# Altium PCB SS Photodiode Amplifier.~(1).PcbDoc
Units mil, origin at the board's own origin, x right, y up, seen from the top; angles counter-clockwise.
Board outline 2000 x 1500 mil, 2 copper layers (Top Layer, Bottom Layer), stack 62 mil thick; 22 components, 10 nets, 61 pads, 2 vias.
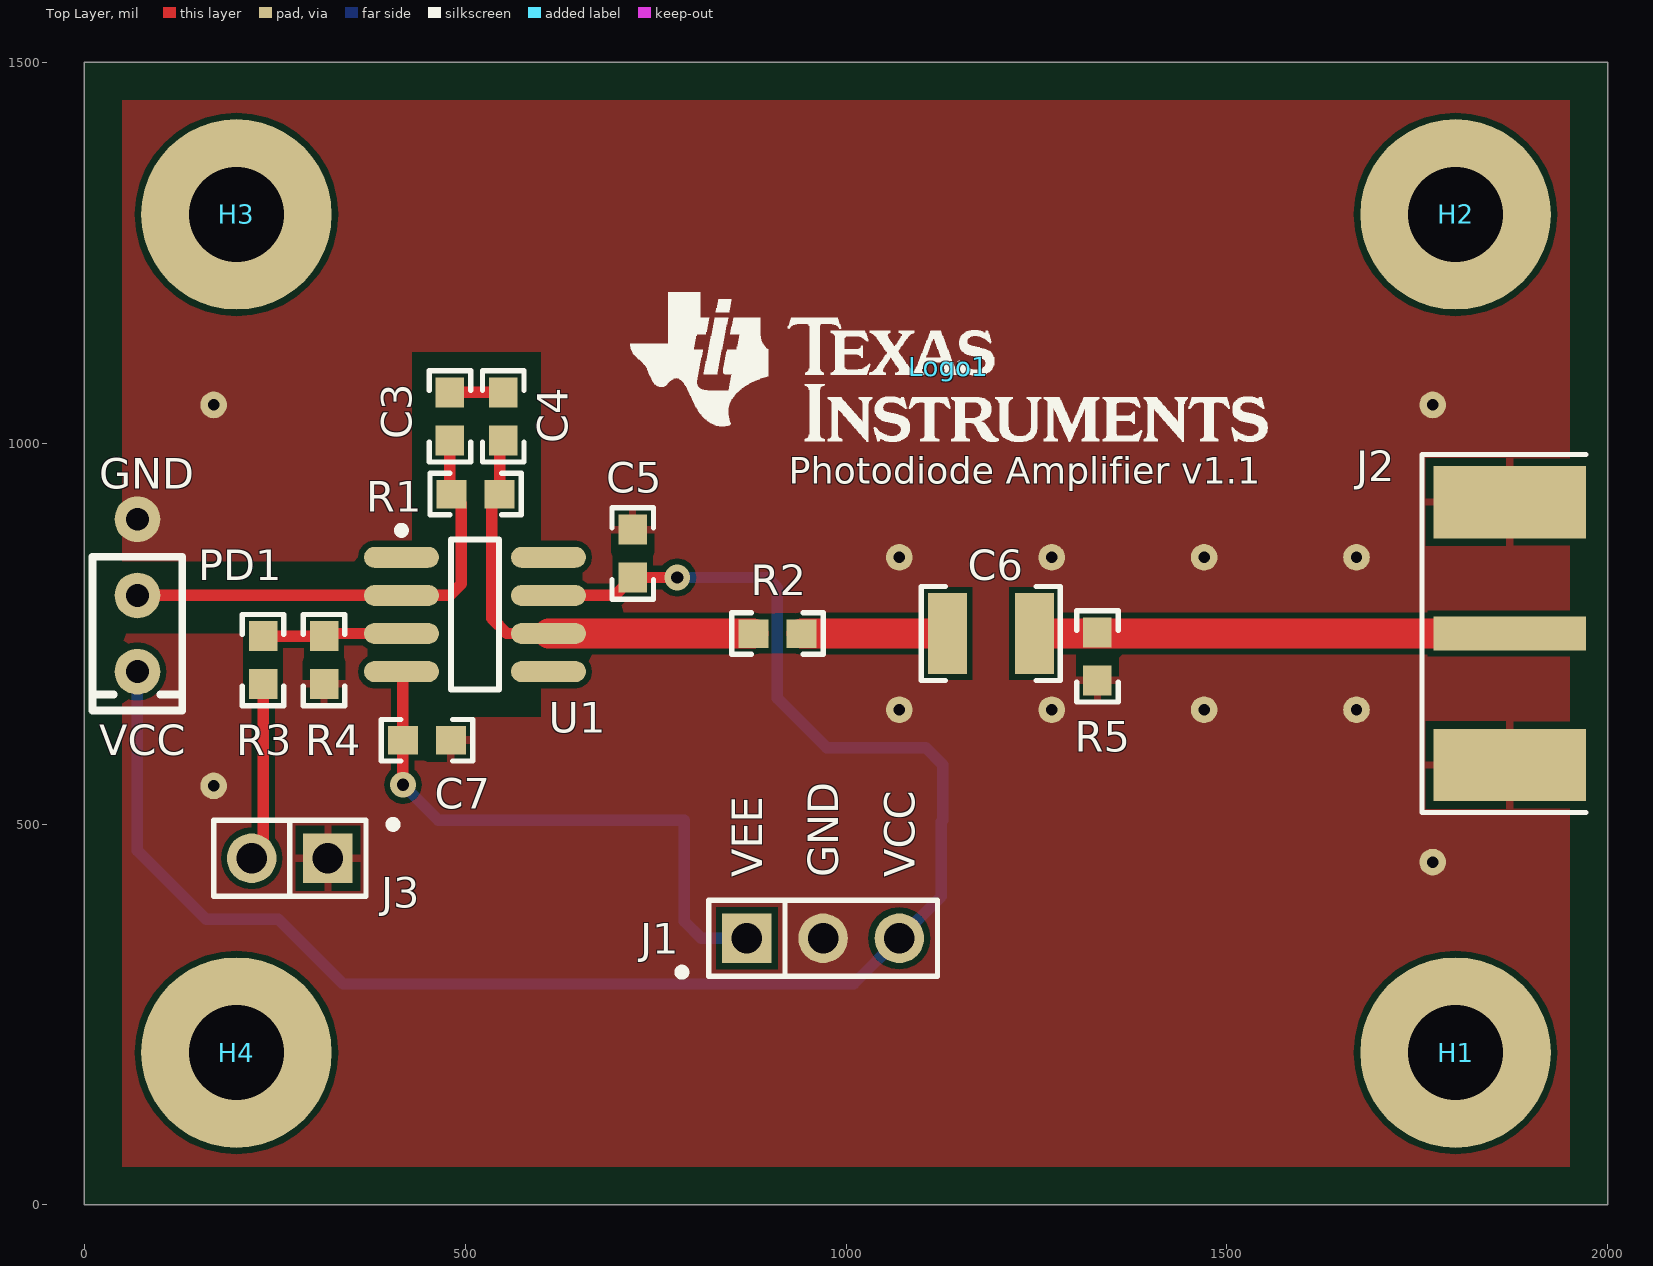
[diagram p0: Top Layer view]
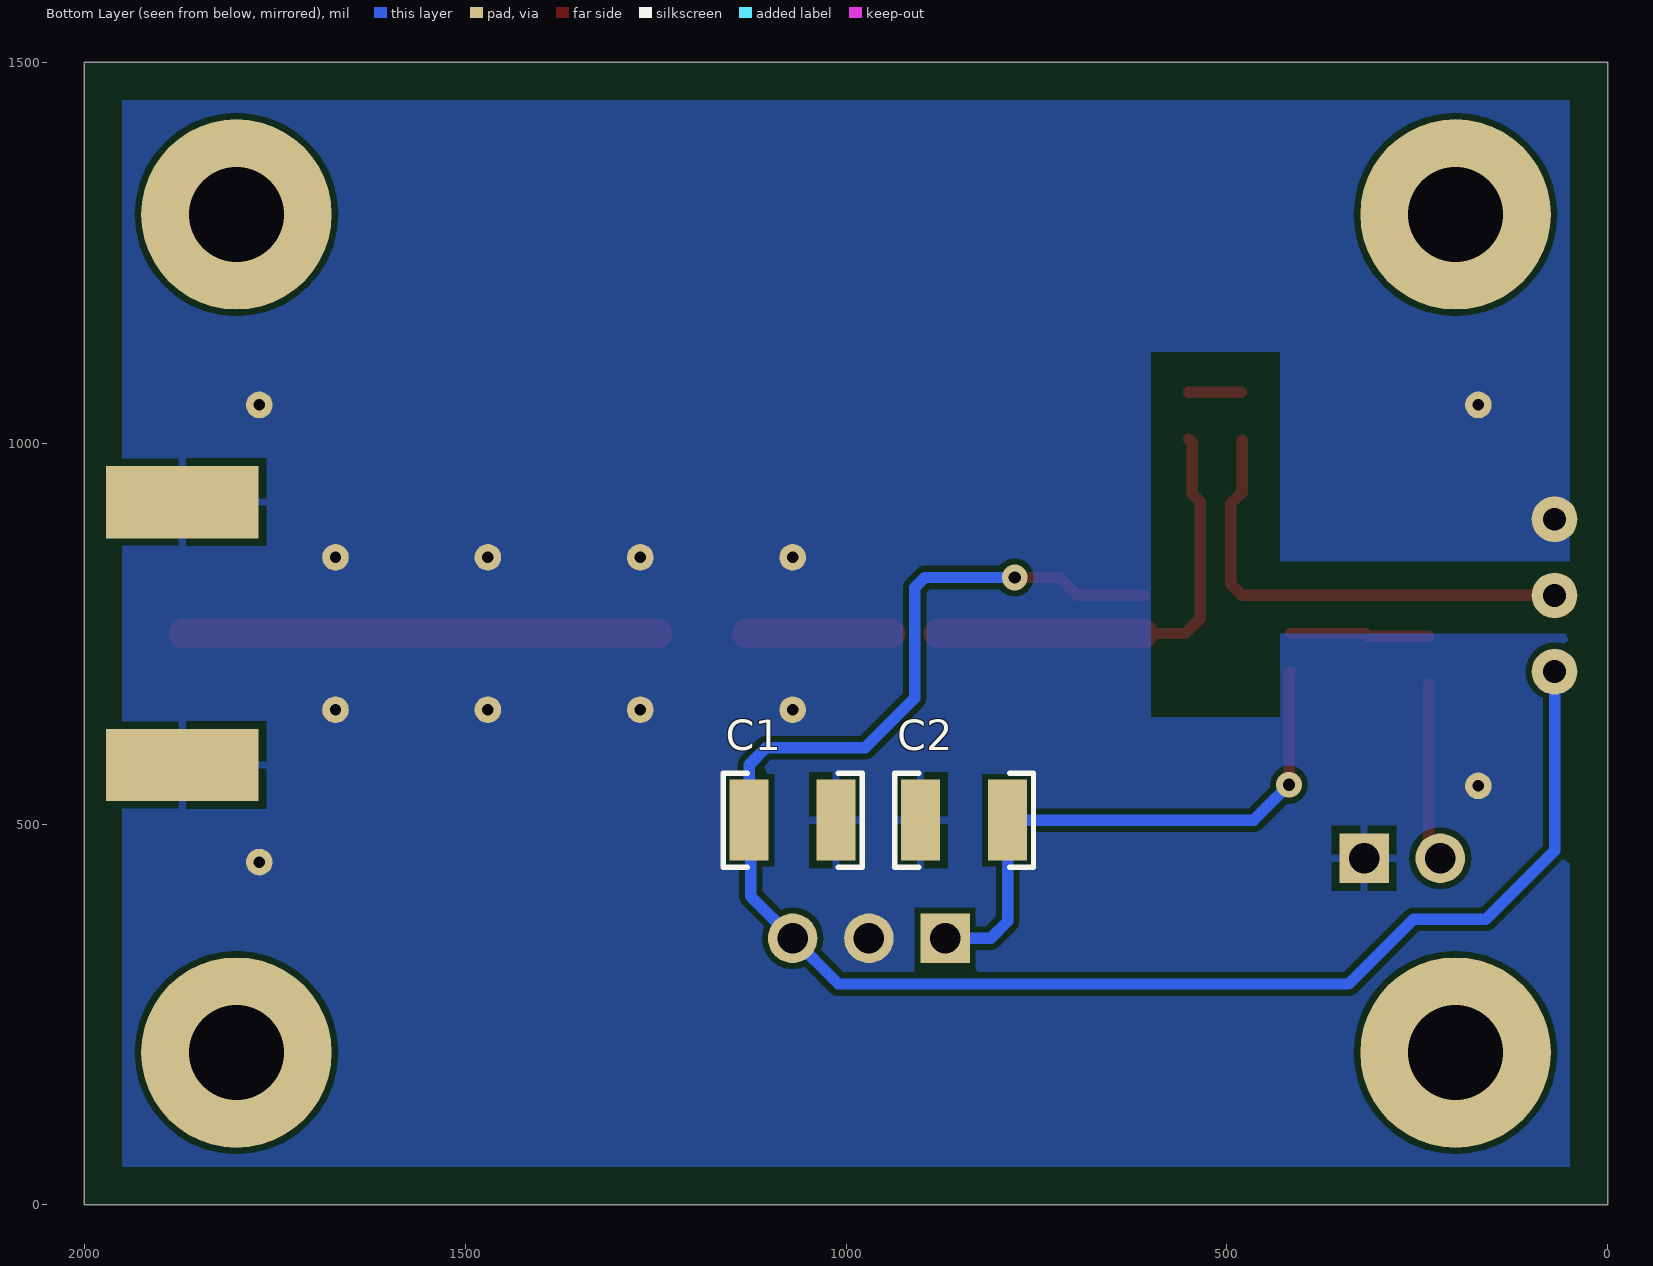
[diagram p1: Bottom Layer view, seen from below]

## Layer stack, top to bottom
Top Layer: signal copper 1.4
Dielectric: core 59.2, FR-4, Dk 4.8
Bottom Layer: signal copper 1.4

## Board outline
0,0 2000,0 2000,1500 0,1500

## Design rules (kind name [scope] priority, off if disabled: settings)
AcuteAngle [All] p1: minimum=4.50000000000000E+0001 checktracksonly=FALSE
AssemblyTestPointUsage [All] p1: valid=2
Clearance "Transmission Line Clearance" [(InNet('NetC3_1') OR InNet('NETC5_1') OR InNet('NETC5_2'))] p1: gap=6
Clearance Clearance_BoardEdge_MountingHoles [OnCopper and InComponentClass('Mounting Holes') vs IsKeepOut] p2: gap=40
Clearance Clearance_BoardEdge_Poly [OnCopper and InPoly vs IsKeepOut] p3: gap=25
Clearance Clearance_BoardEdge [OnCopper and Not InComponentClass('Logo') and not InComponentClass('FiducialMark') and not InRegion(1000,500,4000,800) vs IsKeepOut] p4: gap=75
Clearance [All] p5: gap=8
ComponentClearance ComponentClearance_Logo [InComponentClass(Logo)] p1: gap=50 collisioncheckmode=3 verticalgap=10 showdistances=FALSE
ComponentClearance ComponentClearance_ScrewToNut [(HasFootprint('NY PMS 440 0025 PH')) vs (HasFootprint('Keystone_1902C'))] p2: gap=5 collisioncheckmode=3 verticalgap=10 showdistances=FALSE
ComponentClearance ComponentClearance_MountingHoles [InComponentClass('Mounting Holes')] p3: gap=250 collisioncheckmode=3 verticalgap=100000 showdistances=FALSE
ComponentClearance ComponentClearance_SmallPassives [HasFootprint('0201*') or HasFootprint('0402*') or HasFootprint('0508') or HasFootprint('0603*') or HasFootprint('0612') or HasFootprint('0805*') or HasFootprint('0815*') or HasFootprint('0830*') or HasFootprint('1206*') or HasFootprint('1210*') or HasFootprint('1808*') or HasFootprint('1812*') or HasFootprint('1825*') or HasFootprint('2010*') or HasFootprint('2220*') or HasFootprint('2225*') or HasFootprint('2512*') or HasFootprint('2728*') or HasFootprint('3518*') vs HasFootprint('0201*') or HasFootprint('0402*') or HasFootprint('0508') or HasFootprint('0603*') or HasFootprint('0612') or HasFootprint('0805*') or HasFootprint('0815*') or HasFootprint('0830*') or HasFootprint('1206*') or HasFootprint('1210*') or HasFootprint('1808*') or HasFootprint('1812*') or HasFootprint('1825*') or HasFootprint('2010*') or HasFootprint('2220*') or HasFootprint('2225*') or HasFootprint('2512*') or HasFootprint('2728*') or HasFootprint('3518*')] p4: gap=10 collisioncheckmode=3 verticalgap=10 showdistances=FALSE
ComponentClearance ComponentClearance_THtoSMT [IsThruComponent vs IsSMTComponent] p5: gap=10 collisioncheckmode=3 verticalgap=100000 showdistances=FALSE
ComponentClearance ComponentClearance_THtoTH [IsThruComponent vs IsThruComponent] p6: gap=10 collisioncheckmode=3 verticalgap=100000 showdistances=FALSE
ComponentClearance [All] p7: gap=40 collisioncheckmode=3 verticalgap=10 showdistances=FALSE
DiffPairsRouting [All] p1: maxlimit=100 minlimit=10 mostfreqgap=10 maxuncoupledlength=1000
FabricationTestPointUsage TestPointUsage [All] p1: valid=2 allowmultiple=FALSE
FabricationTestpoint Testpoint [All] p1: side=3 testpointundercomponent=TRUE minsize=40 maxsize=100 preferedsize=60 minholesize=0 maxholesize=40 preferedholesize=32 testpointgrid=1 allowsidetop=TRUE allowsidebottom=TRUE usegrid=TRUE gridtolerance=0.01
FanoutControl Fanout_LCC [IsLCC] p1: bgadir=Out bgaviamode=Centered fanoutstyle=Auto fanoutdirection=Alternating viagrid=1 // Fanout_LCC (Default Rule)
FanoutControl Fanout_BGA [IsBGA] p2: bgadir=Out bgaviamode=Centered fanoutstyle=Auto fanoutdirection=Alternating viagrid=1 // Fanout_BGA (Default Rule)
FanoutControl Fanout_Default [All] p4: bgadir=Out bgaviamode=Centered fanoutstyle=Auto fanoutdirection=Alternating viagrid=1 // Fanout_Default (Default Rule)
FanoutControl Fanout_Small [(CompPinCount < 5)] p5: bgadir=Out bgaviamode=Centered fanoutstyle=Auto fanoutdirection=OutThenIn viagrid=1 // Fanout_Small (Default Rule)
HoleSize [All] p1: absolutevalues=TRUE maxlimit=251 minlimit=8 maxpercent=80.000 minpercent=20.000
MinimumAnnularRing [All] p1: minimumring=9
MinimumSolderMaskSliver MinimumSolderMaskSliver_Logo [InComponentClass('Logo') vs InComponentClass('Logo')] p1: minsoldermaskwidth=0.7
MinimumSolderMaskSliver [All] p2: minsoldermaskwidth=4
PlaneConnect [All] p1: planeconnectstyle=Relief reliefexpansion=10 reliefentries=4 reliefconductorwidth=10 reliefairgap=10
PolygonConnect GNDVia [InPadClass('GNDVia')] p1: connectstyle=Direct reliefconductorwidth=10 reliefentries=4 polygonreliefangle="90 Angle" airgapwidth=10
PolygonConnect "SMA GND" [(InComponent('J1') AND InNet('GND'))] p2: connectstyle=Direct reliefconductorwidth=10 reliefentries=4 polygonreliefangle="90 Angle" airgapwidth=10
PolygonConnect [All] p3: connectstyle=Relief reliefconductorwidth=10 reliefentries=4 polygonreliefangle="90 Angle" airgapwidth=10
RoutingVias [All] p1: holewidth=16 width=34 viastyle="Through Hole" minholewidth=8 minwidth=26 maxholewidth=40 maxwidth=65
SMDToCorner [All] p1: distance=30000
SilkToSilkClearance [All] p1: silktosilkclearance=5
SilkscreenOverComponentPads [All] p1: minsilkscreentomaskgap=5
SolderMaskExpansion [All] p1: expansion=3
Width [All] p1: maxlimit=100 minlimit=6 preferedwidth=15 checkconnectedcopper=TRUE
14 further rules are at their usual default settings.

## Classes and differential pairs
component class Logo: Logo1
component class OPA172PDA_Hardware_ANSI-B: Logo1
component class Header: J1 J3
component class OPA172PDA: C1 C2 C3 C4 C6 C7 H1 H2 H3 H4 J2 J3 PD1 R1 R2 R3 R4 R5 U1
pad class GNDVia: Free-0 Free-1 Free-2 Free-3 Free-4 Free-5 Free-6

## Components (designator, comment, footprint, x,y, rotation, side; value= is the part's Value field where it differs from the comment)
C1 "C1210C106K8PACTU" 1210 1070,505 r180 bottom
C2 "C1210C106K8PACTU" 1210 845,505 r180 bottom
C3 "06033C101KAT2A" 0603 480,1035 r270 top
C4 "06033C101KAT2A" 0603 550,1035 r270 top
C5 "0603YC104JAT2A" 0603 720,855 r270 top
C6 "12103D226MAT2A" 1210 1190,750 r180 top
C7 "0603YC104JAT2A" 0603 450,610 r180 top
H1 "NA" "Mounting Hole" 1800,200 r0 top
H2 "NA" "Mounting Hole" 1800,1300 r0 top
H3 "NA" "Mounting Hole" 200,1300 r0 top
H4 "NA" "Mounting Hole" 200,200 r0 top
J1 "TSW-103-07-G-S" TSW-103-07-G-S 970,350 r0 top
J2 "142-0701-851" Emerson_142-0701-851 1871,750 r270 top
J3 "TSW-102-07-G-S" TSW-102-07-G-S 270,455 r180 top
Logo1 "Texas Instruments" TI_Stacked_Overlay_Small 1135,1100 r0 top
PD1 "PDB-C156" PDB-C156 70,750 r180 top
R1 "CRCW060310K0FKEA" 0603 514,933 r0 top
R2 "CRCW060351R1FKEA" 0603 910,750 r0 top
R3 "CRCW060310R0FKEA" 0603 235,715 r90 top
R4 "CRCW060310R0FKEA" 0603 315,715 r90 top
R5 "CRCW0603100KFKEA" 0603 1330,720 r90 top
U1 "OPA172" M08A_M 513,775 r0 top

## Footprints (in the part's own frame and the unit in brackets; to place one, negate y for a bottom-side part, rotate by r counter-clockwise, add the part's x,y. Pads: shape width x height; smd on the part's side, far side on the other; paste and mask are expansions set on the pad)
0603 [mm] "0603 from SM-752 data"
  rect 1x0.95 smd: 1(-0.8,0) 2(0.8,0)
  silkscreen extent -1.52,-0.69 1.52,0.69, body extent -0.87,-0.47 0.87,0.47, height 0.85
1210 [mm] "1210 from SM-752 data"
  rect 1.3x2.7 smd: 1(-1.45,0) 2(1.45,0)
  silkscreen extent -2.32,-1.57 2.32,1.57, body extent -1.7,-1.35 1.7,1.35, height 1.35
Emerson_142-0701-851 [mil] "Johnson Components"
  rect 45x200 smd: 1(0,0)
  rect 95x200 smd: 2(-172.5,0) 3(172.5,0)
  rect 95x200 smd far side: 4(172.5,0) 5(-172.5,0)
  silkscreen extent -235,-115 235,100, body extent -190,-95 190,487, height 155
M08A_M [mm] "SOIC, 8-Leads, Body 4.9x3.9mm, Pitch 1.27mm, IPC Low Density"
  oval 2.5x0.7 smd: 1(-2.45,1.905) 2(-2.45,0.635) 3(-2.45,-0.635) 4(-2.45,-1.905) 5(2.45,-1.905) 6(2.45,-0.635) 7(2.45,0.635) 8(2.45,1.905)
  silkscreen extent -2.57,-2.5 0.8,2.93, body extent -2,-2.5 2,2.5, height 1.75
"Mounting Hole" [mil]
  round 250 hole 125: 1(0,0)
PDB-C156 [mil] "Photodiode"
  round 60 hole 30: 1(0,50) 2(0,-50)
  silkscreen extent -59,-101 59,101
TI_Stacked_Overlay_Small [mil]
  silkscreen extent -418,-98 418,98
TSW-102-07-G-S [mm] "Samtec 100mil, 1x2, 230 mil above insulator"
  rect 1.65x1.65 hole 1.016 mask+0: 1(-1.27,0)
  round 1.65 hole 1.016 mask+0: 2(1.27,0)
  silkscreen extent -3.57,-1.27 2.54,1.27, body extent -2.54,-1.27 2.54,1.27, height 8.38
TSW-103-07-G-S [mm] "Samtec 100mil, 1x3, 230 mil above insulator"
  rect 1.65x1.65 hole 1.016 mask+0: 1(-2.54,0)
  round 1.65 hole 1.016 mask+0: 2(0,0) 3(2.54,0)
  silkscreen extent -4.83,-1.27 3.81,1.27, body extent -3.81,-1.27 3.81,1.27, height 8.38

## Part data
C1 C2: "CAP, CERM, 10uF, 10V, +/-10%, X5R, 1210"
C3 C4: "CAP, CERM, 100pF, 25V, +/-10%, X7R, 0603"
C5 C7: "CAP, CERM, 0.1uF, 16V, +/-5%, X7R, 0603"
C6: "CAP, CERM, 22uF, 25V, +/-20%, X5R, 1210"
H1 H2 H3 H4: library part "Mounting Hole", "Mounting Hole"
J1: "Header, TH, 100mil, 3x1, Gold plated, 230 mil above insulator"
J2: "Connector, SMT, End launch SMA 50 ohm"
J3: "Header, TH, 100mil, 2x1, Gold plated, 230 mil above insulator"
Logo1: library part TI_Logo, "Texas Instrument Corporate Signature"
PD1: "Photodiode"
R1: "RES, 10.0k ohm, 1%, 0.1W, 0603"
R2: "RES, 51.1 ohm, 1%, 0.1W, 0603"
R3 R4: "RES, 10.0 ohm, 1%, 0.1W, 0603"
R5: "RES, 100k ohm, 1%, 0.1W, 0603"

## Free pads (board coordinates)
  round 60 hole 30: 0(70,900)
  round 35 hole 15: 0(1070,650) 0(1670,850) 0(1770,450) 1(1470,850) 1(1770,1050) 2(170,1050) 2(1270,850) 3(170,550) 3(1070,850) 4(1670,650) 5(1470,650) 6(1270,650)

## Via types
v1: diameter 34, hole 16, Top Layer to Bottom Layer, 2 vias

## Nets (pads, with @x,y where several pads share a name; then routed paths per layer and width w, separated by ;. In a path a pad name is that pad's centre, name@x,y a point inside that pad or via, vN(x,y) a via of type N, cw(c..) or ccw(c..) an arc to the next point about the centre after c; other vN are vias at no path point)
GND: C1.2 C2.1 C5.1 C7.1 J1.2 J2.2 J2.3 J2.4 J2.5 J3.1 pad.0 pad.1 pad.2 pad.3 pad.4 pad.5 pad.6 R4.1 R5.1
NetC3_1: C3.1 C4.1 | length 68.5
  Top Layer w15: C3.1@481.5,1066.5 C4.1
NetC3_2: C3.2 PD1.2 R1.1 U1.2 | length 622.9
  Top Layer w15: PD1.2 U1.2 480,800 495,815 495,920.5 R1.1 ; R1.1@480,935 C3.2
NetC4_2: C4.2 R1.2 R2.1 U1.6 | length 592.5
  Top Layer w15: C4.2@550,1005 545.5,1000.5 R1.2 535,922.5 535,770 555,750 U1.6
  Top Layer w39: U1.6@610,750 R2.1
NetC6_1: C6.1 J2.1 R5.2 | length 622.9
  Top Layer w39: C6.1 J2.1@1870,750
NetC6_2: C6.2 R2.2 | length 188.5
  Top Layer w39: R2.2 C6.2@1130,750
NetJ3_2: J3.2 R3.1 | length 234.7
  Top Layer w15: J3.2 235,470 R3.1
NetR3_2: R3.2 R4.2 U1.3 | length 183
  Top Layer w15: R3.2 R4.2 318.5,750 U1.3
VCC: C1.1 C5.2 J1.3 PD1.1 U1.7 | length 2295
  Top Layer w15: U1.7 696.5,800 C5.2 v1(778.5,823.5)
  Bottom Layer w15: PD1.1 70,465 160,375 255,375 340,290 1010,290 J1.3 1125,405 C1.1@1125,502.91 ; v1(778.5,823.5) 896.5,823.5 910,810 910,665 975,600 1105,600 1127.09,577.91 C1.1
VEE: C2.2 C7.2 J1.1 U1.4 | length 762.1
  Top Layer w15: U1.4 418.5,698.04 C7.2 v1(418.5,551.5)
  Bottom Layer w15: v1(418.5,551.5) 465,505 C2.2 787.91,372.09 810,350 J1.1
pads on no net: H1.1 H2.1 H3.1 H4.1 U1.1 U1.5 U1.8

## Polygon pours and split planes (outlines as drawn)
GND on Top Layer "Top Layer GND" (solid, pour order 4): 50,1450 50,50 1950,50 1950,1450
GND on Bottom Layer "Bottom Layer GND" (solid, pour order 3): 50,1450 50,50 1950,50 1950,1450

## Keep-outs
Keep-Out Layer:
  lines w10: -5,3450 cw(c0,3450) 0,3455 ; -5,3450 cw(c0,3450) 0,3455 ; -5,3450 cw(c0,3450) 0,3455 ; -5,3450 cw(c0,3450) 0,3455 ; -5,3450 cw(c0,3450) 0,3455 ; -5,3450 cw(c0,3450) 0,3455 ; 4950,-5 ccw(c4950,0) 4955,0 ; 4950,-5 ccw(c4950,0) 4955,0 ; 4950,-5 ccw(c4950,0) 4955,0 ; 4950,-5 ccw(c4950,0) 4955,0 ; 4950,-5 ccw(c4950,0) 4955,0 ; 4950,-5 ccw(c4950,0) 4955,0 ; 4950,3455 cw(c4950,3450) 4955,3450 ; 4950,3455 cw(c4950,3450) 4955,3450 ; 4950,3455 cw(c4950,3450) 4955,3450 ; 4950,3455 cw(c4950,3450) 4955,3450 ; 4950,3455 cw(c4950,3450) 4955,3450 ; 4950,3455 cw(c4950,3450) 4955,3450
  text ".Layer_Name" at 577,-858.49 h60

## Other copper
Top Layer:
  pour cut-out: 430,1120 430,640 600,640 600,1120
  pour cut-out: 20,750 430,750 430,845 20,845
Bottom Layer:
  pour cut-out: 430,1120 430,640 600,640 600,1120
  pour cut-out: 20,750 430,750 430,845 20,845

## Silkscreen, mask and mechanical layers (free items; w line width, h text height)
Top Overlay:
  text "GND" at 20,940 h40
  text "Photodiode Amplifier v1.1" at 925,935 h60
  text "VCC" at 20,590 h40
  text "VEE" at 890,430 h40 r90
  text "GND" at 990,430 h40 r90
  text "VCC" at 1090,430 h40 r90
Top Paste:
  text ".Layer_Name" at 577,-858.49 h60
Bottom Paste:
  text ".Layer_Name" at 577,-858.49 h60
Drill Guide:
  text ".Layer_Name" at 577,-858.49 h60
M1 Board Outline:
  the board outline again, w10
M2 Board Dimensions:
  rectangle: 124.5,-410.5 499.5,-285.5
  rectangle: -0.5,-285.5 124.5,-160.5
  lines w7: -0.5,-285.5 999.5,-285.5 ; 124.5,-410.5 124.5,-160.5 ; 249.5,-410.5 249.5,-160.5 ; 499.5,-410.5 499.5,-160.5 ; 749.5,-410.5 749.5,-160.5 ; -0.5,-410.5 -0.5,-160.5 999.5,-160.5 999.5,-410.5 -0.5,-410.5
  lines w10: -0.5,-475.5 -0.5,-455.5 ; 59.5,-485.5 -0.5,-465.5 ; 59.5,-445.5 -0.5,-465.5 ; 223.58,-465.5 -0.5,-465.5 ; 775.42,-465.5 999.5,-465.5 ; 939.5,-485.5 999.5,-465.5 ; 939.5,-445.5 999.5,-465.5 ; 999.5,-475.5 999.5,-455.5
  text "1000 (mil)" at 233.58,-501.49 h60
  text ".Layer_Name" at 577,-858.49 h60
M3 3D STEP Top:
  text ".Layer_Name" at 577,-858.49 h60
M4 3D STEP Bottom:
  text ".Layer_Name" at 577,-858.49 h60
M5 Assembly Top:
  lines w7: 4210,929.26 5335,929.26 ; 4210,1051.76 5332.5,1051.76 ; 4910,1171.76 4210,1171.76 5335,1171.76 ; 5139,353 5139,-9.5 ; 5454,-9.5 5454,353 ; 5839,-9.5 5139,-9.5 ; 6264,353 6264,-9.5 5139,-9.5
  lines w10: -292,-930.17 6308,-930.17 ; -292,-726.83 6310,-726.83 ; -292,-523.5 -292,-1133.5 3713,-1133.5 6310,-1133.5 6310,-523.5 -291.5,-523.5 -291.5,-1133.5 1284,-1133.5 ; 2173,-1133.5 2173,-523.5 ; 3440,-726.83 3440,-523.5 ; 4280,-726.83 4280,-523.5 ; 4902,-1140 4902,-937.17
  text "TABLE 1" at 4597.5,1206.76 h40
  text "Label text" at 4662,1112 h40
  text "Variant" at 4235,1096.76 h40
  text "001" at 4302.5,976.76 h40
  text "ChangeMe!" at 4580,974.26 h40
  text "002" at 4302.5,851.76 h40
  text "ChangeMe!" at 4575,849.26 h40
  text "COMPONENTS MARKED 'DNP' SHOULD NOT BE POPULATED, AND MAY NOT BE IN BILL OF MATERIALS" at 1153.5,-318.5 h60
  text "ASSEMBLY VARIANT:" at 1153,-434 h60
  text ".VariantName" at 2189,-434 h60
  text "PCB VIEWED FROM TOP SIDE" at -228.5,-655.67 h60
  text "BOARD #:" at 2248,-655.67 h60
  text ".PRJ_Number" at 2793.5,-655.67 h60
  text "REV:" at 3638,-655.67 h60
  text ".PCB_Rev" at 3929.5,-655.67 h60
  text "SVN REV:" at 4476,-655.67 h60
  text ".VersionControl_RevNumber" at 4982,-655.67 h60
  text "IGNORE ->" at -228.5,-858.49 h60
  text "PLOT NAME =" at -228.5,-1064.34 h60
  text ".plot_File_Name" at 577,-1064.34 h60
  text "GENERATED    :" at 2250,-1064.34 h60
  text ".Print_Date" at 3119.5,-1064.34 h60
  text ".Print_Time" at 3848.5,-1064.34 h60
  text "TEXAS INSTRUMENTS" at 5113,-1064.34 h60
M6 Assembly Bottom:
  lines w10: -292.5,-727.33 6309.5,-727.33 ; -290.5,-930.67 6309.5,-930.67 ; 1115.5,-1140.5 1115.5,-937.67 ; 1737.5,-727.33 1737.5,-524 ; 2577.5,-727.33 2577.5,-524 ; 3844.5,-1134 3844.5,-524 ; 4733.5,-1134 6309,-1134 6309,-524 -292.5,-524 -292.5,-1134 2304.5,-1134 6309.5,-1134 6309.5,-524
  text "COMPONENTS MARKED 'DNP' SHOULD NOT BE POPULATED, AND MAY NOT BE IN BILL OF MATERIALS" at 6102,-318 h60
  text ".VariantName" at 5058,-434 h60
  text "ASSEMBLY VARIANT:" at 6097,-434 h60
  text ".VersionControl_RevNumber" at 1035.5,-656.17 h60
  text "SVN REV:" at 1541.5,-656.17 h60
  text ".PCB_Rev" at 2088,-656.17 h60
  text "REV:" at 2379.5,-656.17 h60
  text ".PRJ_Number" at 3224,-656.17 h60
  text "BOARD #:" at 3769.5,-656.17 h60
  text "PCB VIEWED FROM BOTTOM SIDE" at 6246,-656.17 h60
  text "IGNORE ->" at 2547.85,-858.49 h60
  text "TEXAS INSTRUMENTS" at 904.5,-1064.84 h60
  text ".Print_Time" at 2169,-1064.84 h60
  text ".Print_Date" at 2898,-1064.84 h60
  text "GENERATED    :" at 3767.5,-1064.84 h60
  text ".plot_File_Name" at 5440.5,-1064.84 h60
  text "PLOT NAME =" at 6246,-1064.84 h60
M9 Title Sheet:
  drawing of 57 lines, arcs and shapes, not listed
  text "1" at 739.84,8036.5 h70
  text "2" at 3235.5,8036.5 h70
  text "3" at 5724.84,8036.5 h70
  text "4" at 8231.51,8036.5 h70
  text "5" at 10730.5,8036.5 h70
  text "6" at 13235.5,8036.5 h70
  text "A" at -416.5,6893.5 h70
  text "A" at 14383.5,6893.5 h70
  text "B" at -416.5,4513.5 h70
  text "B" at 14383.5,4513.5 h70
  text "C" at -416.5,2138.5 h70
  text "C" at 14383.5,2138.5 h70
  text "PROJECT TITLE:" at 11343.5,277.5 h45
  text ".PRJ_Title" at 11393.5,144.17 h70
  text "DESIGNED FOR:" at 11343.5,-23.5 h45
  text ".PRJ_Customer" at 11393.5,-163.5 h70
  text "D" at -416.5,-231.5 h70
  text "D" at 14383.5,-231.5 h70
  text "FILE NAME:" at 11343.5,-323.5 h45
  text ".PCB_File_Name_No_Path" at 11393.5,-443.5 h70
  text "Texas Instruments (TI) and/or its licensors do not warrant the accuracy or completeness of this specification" at 6374,-605.34 h45
  text "ENGINEER:" at 11343.5,-613.5 h45
  text "LAYOUT BY:" at 12848.5,-613.5 h45
  text "or any information contained therein. TI and/or its licensors do not warrant that this design will meet" at 6329.01,-718 h45
  text ".PRJ_Engineer" at 11393.5,-768.49 h70
  text ".PCB_Layout" at 12899,-768.49 h70
  text "the specifications, will be suitable for your application or fit for any particular purpose, or will operate in" at 6329.01,-830.67 h45
  text ".Layer_Name" at 577,-858.49 h60
  text "ALTIUM DESIGNER VERSION:" at 12848.5,-923.5 h45
  text "an implementation. TI and/or its licensors do not warrant that the design is production worthy. You should" at 6329.01,-943.33 h45
  text "completely validate and test your design implementation to confirm the system functionality for your application." at 6374,-1056 h45
  text ".print_Scale" at 11393.5,-1056.83 h70
  text ".Application_BuildNumber" at 12899,-1056.83 h70
  text "1" at 739.84,-1263.5 h70
  text "2" at 3235.5,-1263.5 h70
  text "3" at 5724.84,-1263.5 h70
  text "4" at 8231.51,-1263.5 h70
  text "5" at 10730.5,-1263.5 h70
  text "6" at 13235.5,-1263.5 h70
M10 Fab Notes:
  drawing of 203 lines, arcs and shapes, not listed
  text "DESIGN INFORMATION" at 12381.02,6810 h60
  text "(REFER ALSO ARRAY/PANEL PROFILING INFORMATION)" at 12019.46,6648.29 h60
  text "BOARD SIZE" at 11333.46,6644 h60
  text "3450MIL" at 11795.78,6516.18 h60
  text "X" at 12301.46,6516.18 h60
  text "4950MIL" at 12532.78,6516.18 h60
  text "Number of Layers :" at 11736.46,6319 h60
  text "2" at 12831.27,6309 h60
  text "MIN. TRACK WIDTH:" at 11736.46,6180 h60
  text "8" at 12832.7,6180 h60
  text "MIL" at 12987.46,6180 h60
  text "MIN. CLEARANCE:" at 11736.46,6048 h60
  text "8" at 12832.7,6048 h60
  text "MIL" at 12987.46,6048 h60
  text "MIN. VIA PAD SIZE:" at 11736.46,5916 h60
  text "24" at 12802.71,5916 h60
  text "MIL" at 12987.46,5916 h60
  text "0.05mm (2MIL)" at 12431.46,5774.29 h60
  text "MINIMUM ANNULAR RING" at 11407.23,5770 h60
  text "EXTERNAL" at 13139.46,5770 h60
  text "PER" at 11607.23,5652 h60
  text "IPC-D-275 CLASS 2 LEVEL C" at 11827.23,5652 h60
  text "MIL, HOLES" at 13315.46,5539.71 h60
  text "+/-" at 12923,5539 h60
  text "+/-" at 13777,5539 h60
  text "REGISTRATION TOLERANCES:" at 11407.23,5534 h60
  text "METAL" at 12607,5534 h60
  text "5" at 13183.2,5534 h60
  text "3" at 14016.2,5534 h60
  text "MIL" at 14132.46,5534 h60
  text "MATERIAL:" at 11332.46,5324.54 h60
  text "FR-4 High Tg" at 12318.9,5184.21 h60
  text "FR-4" at 11793.46,5175.64 h60
  text "X" at 12165.46,5175.64 h60
  text "OTHER" at 13241.46,5175.64 h60
  text "62 MIL (1.6mm) +/-10%" at 12073.56,5012.92 h60
  text "THICKNESS:" at 11407.23,5008.64 h60
  text "X" at 11945.4,5008.64 h60
  text "OTHER" at 13358.46,5008.64 h60
  text "TOLERANCE:" at 11407.23,4850.64 h60
  text "X" at 12246.53,4850.64 h60
  text "ANSI IPC-6012 TYPE 3 CLASS 2" at 12433.48,4850.64 h60
  text "OTHER +/-" at 12433.46,4694.64 h60
  text "BOW & TWIST:" at 11407.23,4537.64 h60
  text "X" at 12246.53,4537.64 h60
  text "ANSI IPC-6012 TYPE 3 CLASS 2" at 12433.48,4537.64 h60
  text "OTHER +/-" at 12433.46,4379.13 h60
  text "COPPER THICKNESS (FINISHED):" at 11332.46,4243.64 h60
  text "1.4MIL (1oz)" at 12212.46,4090.92 h60
  text "2MIL (1.4oz)" at 12979.46,4090.92 h60
  text "2.8MIL (2oz)" at 13706.46,4090.92 h60
  text "OUTER:" at 11689.46,4086.64 h60
  text "X" at 12084,4086 h60
  text "1.4MIL (1oz)" at 12562.46,3933.92 h60
  text "2.8MIL (2oz)" at 13406.46,3933.92 h60
  text "INNER SIGNAL:" at 11689.46,3929.64 h60
  text "X" at 12435.42,3929.64 h60
  text "DRILLING:" at 11332.46,3790.64 h60
  text "REFERENCE:" at 11407.23,3673.64 h60
  text "X" at 12055.46,3673.64 h60
  text "AS SHOWN" at 12242.46,3673.64 h60
  text "X" at 12956.46,3673.64 h60
  text "NC_DRILL FILES" at 13093.46,3673.64 h60
  text "PTH MIN COPPER THICKNESS:" at 11407.23,3515.64 h60
  text "X" at 12757.46,3515.64 h60
  text "1MIL" at 12894.46,3515.64 h60
  text "OTHER" at 13391.46,3515.64 h60
  text "BOARD FINISH:" at 11332.46,3356.64 h60
  text "SILKSCREEN:" at 11487.68,3238.64 h60
  text "X" at 12436.46,3238.64 h60
  text "TOP" at 12562.46,3238.64 h60
  text "X" at 12946.46,3238.64 h60
  text "BOTTOM" at 13073.46,3238.64 h60
  text "SILKSCREEN COLOR:" at 11487.68,3071.64 h60
  text "X" at 12435.42,3071.64 h60
  text "WHITE" at 12562.46,3071.64 h60
  text "OTHER" at 13073.46,3071.64 h60
  text "SOLDER RESIST COLOR:" at 11487.68,2901.64 h60
  text "X" at 12055.42,2742.44 h60
  text "GREEN" at 12182.46,2742.44 h60
  text "BLUE" at 12773.46,2742.44 h60
  text "OTHER" at 13311.46,2742.44 h60
  text "IMMERSION GOLD (ENIG)" at 12393.46,2553.92 h60
  text "SURFACE FINISH:" at 11332.46,2549.64 h60
  text "X" at 12206.51,2549.64 h60
  text "Pb-FREE HASL" at 13625.75,2549.64 h60
  text "OTHER" at 12393.46,2392.64 h60
  text "ARRAY/PANEL:" at 11332.46,2213.64 h60
  text "CUT AND TRIM PER MECH LAYER 1" at 12393.46,2209.35 h60
  text "N.C. ROUTE" at 12393.46,2057.64 h60
  text "X" at 13072.46,2057.64 h60
  text "V. SCORE" at 13259.46,2057.64 h60
  text "CERTIFICATION:" at 11332.46,1920.64 h60
  text "MATERIALS AND WORKMANSHIP FOR ALL PCBS" at 12057.46,1920.64 h60
  text "TO MEET OR EXCEED THE REQUIREMENTS OF:" at 12057.46,1822.64 h60
  text "X" at 11683.96,1686.13 h60
  text "ANSI IPC-A-600F CLASS ->" at 11822.96,1686.13 h60
  text "X" at 13462.02,1686.13 h60
  text "2" at 13580.96,1686.14 h60
  text "1" at 13265.96,1684.64 h60
  text "3" at 13934.96,1684.64 h60
  text "X" at 11686.02,1526.64 h60
  text "UL 94V-0" at 11822.96,1526.64 h60
  text "X" at 12498.02,1526.64 h60
  text "RoHS" at 12634.96,1526.64 h60
  text "OTHER" at 13279.36,1526.64 h60
  text "PER ORDER" at 13676.42,1526.64 h60
  text "ADDITIONAL REQUIREMENTS:" at 11332.46,1385.64 h60
  text "MICROSECTION:" at 11407.23,1270.64 h60
  text "YES" at 12312.96,1270.64 h60
  text "REQUIRED" at 13174.46,1114.49 h60
  text "BARE BOARD ELEC. TEST:" at 11407.23,1111.64 h60
  text "NONE" at 12712.96,1111.64 h60
  text "X" at 13047.46,1111.64 h60
  text "PER ORDER" at 13766.46,1111.64 h60
  text "MANUFACTURER'S ID/LOGO:" at 11407.23,954.64 h60
  text "RAIL" at 12872.96,950.35 h60
  text "X" at 13247.46,950.35 h60
  text "METAL" at 13364.77,950.35 h60
  text "SILK" at 13876.46,950.35 h60
  text ".Layer_Name" at 577,-858.49 h60
M11 Gerber Information:
  lines w10: -292,-930.17 6308,-930.17 ; -292,-726.83 6310,-726.83 ; -292,-523.5 -292,-1133.5 3713,-1133.5 6310,-1133.5 6310,-523.5 -291.5,-523.5 -291.5,-1133.5 1284,-1133.5 ; 2173,-1133.5 2173,-523.5 ; 3440,-726.83 3440,-523.5 ; 4280,-726.83 4280,-523.5 ; 4902,-1140 4902,-937.17
  text "ALL ARTWORK VIEWED FROM TOP SIDE" at -228.5,-655.67 h60
  text "BOARD #:" at 2248,-655.67 h60
  text ".PRJ_Number" at 2793.5,-655.67 h60
  text "REV:" at 3638,-655.67 h60
  text ".PCB_Rev" at 3929.5,-655.67 h60
  text "SVN REV:" at 4476,-655.67 h60
  text ".VersionControl_RevNumber" at 4982,-655.67 h60
  text "LAYER NAME =" at -228.5,-858.49 h60
  text "PLOT NAME =" at -228.5,-1064.34 h60
  text ".plot_File_Name" at 577,-1064.34 h60
  text "GENERATED    :" at 2250,-1064.34 h60
  text ".Print_Date" at 3119.5,-1064.34 h60
  text ".Print_Time" at 3848.5,-1064.34 h60
  text "TEXAS INSTRUMENTS" at 5113,-1064.34 h60
M12 Stackup:
  lines w6: 11360,7460 13910,7460 ; 11360,7564.4 13910,7564.4 ; 11300,6975 ccw(c11334,6975) 11334,6941 13936,6941 ccw(c13936,6975) 13970,6975 13970,7681 ccw(c13936,7681) 13936,7715 11334,7715 ccw(c11334,7681) 11300,7681 11300,6975
  text "The Stackup Legend below this is static." at 11605.5,7874.5 h60
  text "If you change the stackup, update the Legend." at 11615.5,7784.5 h60
  text "Layer Stack Up Detail for: Ref_Design.PcbDoc" at 11360,7597.1 h57
  text "Layer" at 11360,7525.4 h24
  text "Gerber" at 12255.81,7525.4 h24
  text "Copper" at 12819.33,7525.4 h24
  text "Dielectric" at 13422.04,7525.4 h24
  text "Name" at 11360,7477.4 h24
  text "Document" at 12255.81,7477.4 h24
  text "Thickness" at 12819.33,7477.4 h24
  text "Material" at 13422.04,7477.4 h24
  text "Top Solder Mask" at 11360,7384.44 h34
  text "(.GTS)" at 12255.81,7384.44 h34
  text "Solder Resist" at 13422.04,7384.44 h34
  text "Top Layer" at 11360,7287.69 h34
  text "(.GTL)" at 12255.81,7287.69 h34
  text "1.4mil" at 12819.33,7287.69 h34
  text "FR-4" at 13422.04,7239.31 h34
  text "Bottom Layer" at 11360,7190.94 h34
  text "(.GBL)" at 12255.81,7190.94 h34
  text "1.4mil" at 12819.33,7190.94 h34
  text "Bottom Solder Mask" at 11360,7094.19 h34
  text "(.GBS)" at 12255.81,7094.19 h34
  text "Solder Resist" at 13422.04,7094.19 h34
  text ".Layer_Name" at 577,-858.49 h60
M13 Component Bodies Top:
  text ".Layer_Name" at 577,-858.49 h60
M14 Component Bodies Bottom:
  text ".Layer_Name" at 577,-858.49 h60
M15 Courtyards Top:
  text ".Layer_Name" at 577,-858.49 h60
M16 Courtyards Bottom:
  text ".Layer_Name" at 577,-858.49 h60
